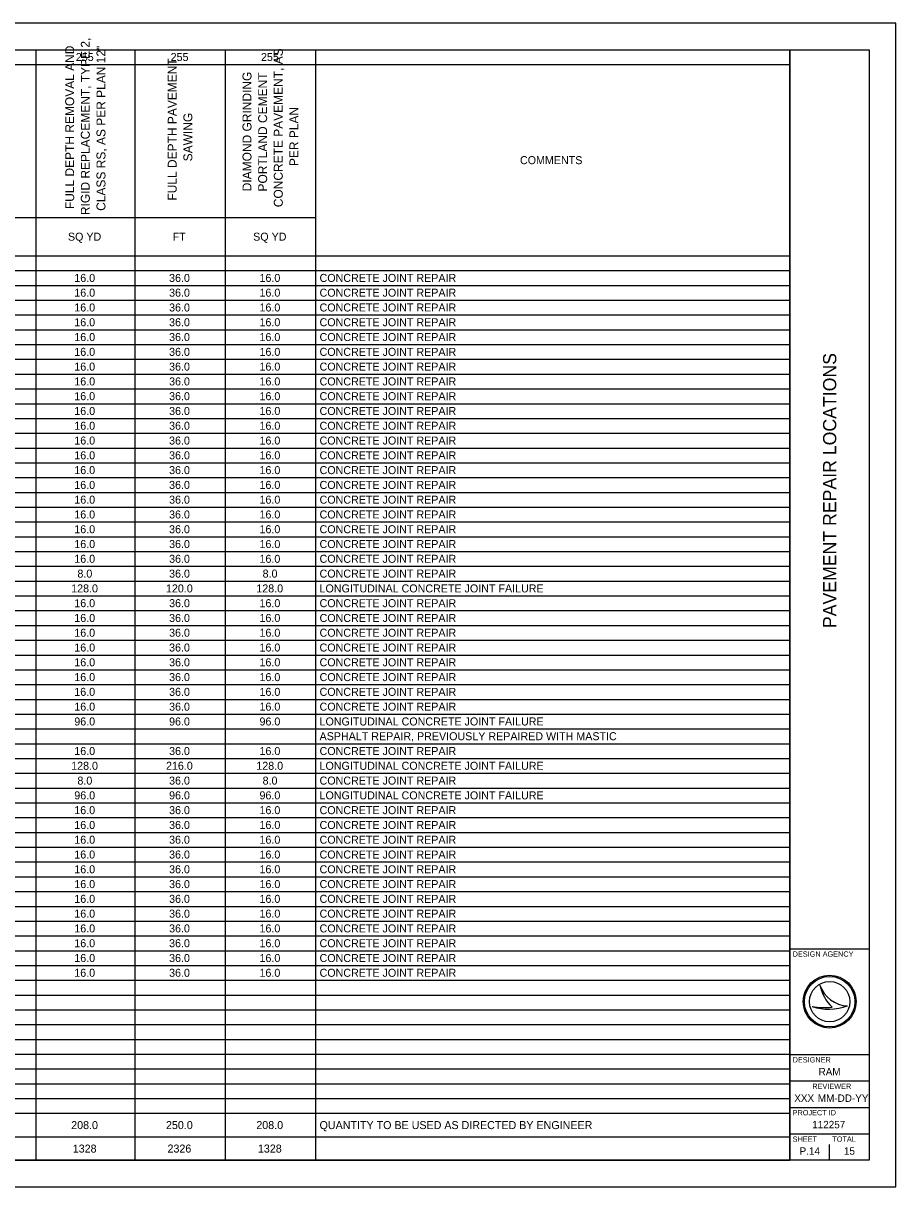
# Model space of a CAD drawing. Extents: x 0 to 34, y 0 to 22.
# Drawn here: x 17.5 to 34, y 0 to 22 of the extents above; entities that cross this region are included whole.
import ezdxf

# ---------------------------------------------------------------- set-up
doc = ezdxf.new("R2010")
doc.units = 0
for name, color, linetype in [('SH_Border', 7, 'Continuous'), ('SH_Cut_Line', 7, 'Continuous'), ('SH_Data', 7, 'Continuous'), ('SH_Text', 7, 'Continuous')]:
    doc.layers.add(name, color=color, linetype=linetype)

msp = doc.modelspace()

# ---------------------------------------------------------------- linework, layer by layer
at = {"layer": 'SH_Border'}
for p, q in [((32, 0.5), (32, 21.5)), ((32, 4.5), (33.5, 4.5)), ((32, 2.5), (33.5, 2.5)), ((32, 2), (33.5, 2)), ((32, 1.5), (33.5, 1.5)), ((32, 1), (33.5, 1))]:
    msp.add_line(p, q, dxfattribs=at)
msp.add_lwpolyline([(1.5, 21.5), (33.5, 21.5), (33.5, 0.5), (1.5, 0.5)], close=True, dxfattribs=at)
at = {"layer": 'SH_Cut_Line'}
msp.add_lwpolyline([(0, 0), (34, 0), (34, 22), (0, 22)], close=True, dxfattribs=at)
at = {"layer": 'SH_Data'}
for p, q in [((32.567, 3.81), (32.567, 3.81)), ((32.417, 3.41), (32.417, 3.41)), ((32.75, 3.5), (32.75, 3.5)), ((33.087, 3.419), (33.087, 3.419)), ((32.375, 0.675), (32.375, 0.675)), ((32.75, 0.5), (32.75, 0.8))]:
    msp.add_line(p, q, dxfattribs=at)
for radius in [0.5, 0.477, 0.477, 0.382]:
    msp.add_circle((32.75, 3.5), radius, dxfattribs=at)
for centre, radius, start, end in [((33.116, 3.998), 0.58, 198.9257, 198.9319), ((33.347, 3.97), 0.796, 191.6379, 191.6421), ((33.116, 3.998), 0.58, 198.9319, 267.1657), ((33.347, 3.97), 0.796, 191.6421, 226.0947), ((32.739, 4.37), 1.013, 251.4576, 290.0832), ((32.648, 4.654), 1.266, 259.4964, 259.4995), ((32.739, 4.37), 1.013, 251.4527, 251.4576), ((32.648, 4.654), 1.266, 259.4995, 276.6672)]:
    msp.add_arc(centre, radius, start, end, dxfattribs=at)
at = {"layer": 'SH_Text'}
for p, q in [((1.5, 21.5), (32, 21.5)), ((17.734, 21.5), (17.734, 0.5)), ((19.609, 21.5), (19.609, 0.5)), ((21.319, 21.5), (21.319, 0.5)), ((23.028, 21.5), (23.028, 21.22)), ((32, 21.5), (32, 0.5)), ((1.5, 21.22), (32, 21.22)), ((23.028, 21.22), (23.028, 17.603)), ((8.946, 18.326), (23.028, 18.326)), ((1.5, 17.603), (32, 17.603)), ((23.028, 17.603), (23.028, 1.388)), ((1.5, 17.323), (32, 17.323)), ((1.5, 17.043), (32, 17.043)), ((1.5, 16.764), (32, 16.764)), ((1.5, 16.484), (32, 16.484)), ((1.5, 16.205), (32, 16.205)), ((1.5, 15.925), (32, 15.925)), ((1.5, 15.646), (32, 15.646)), ((1.5, 15.366), (32, 15.366)), ((1.5, 15.087), (32, 15.087)), ((1.5, 14.807), (32, 14.807)), ((1.5, 14.527), (32, 14.527)), ((1.5, 14.248), (32, 14.248)), ((1.5, 13.968), (32, 13.968)), ((1.5, 13.689), (32, 13.689)), ((1.5, 13.409), (32, 13.409)), ((1.5, 13.13), (32, 13.13)), ((1.5, 12.85), (32, 12.85)), ((1.5, 12.57), (32, 12.57)), ((1.5, 12.291), (32, 12.291)), ((1.5, 12.011), (32, 12.011)), ((1.5, 11.732), (32, 11.732)), ((1.5, 11.452), (32, 11.452)), ((1.5, 11.173), (32, 11.173)), ((1.5, 10.893), (32, 10.893)), ((1.5, 10.614), (32, 10.614)), ((1.5, 10.334), (32, 10.334)), ((1.5, 10.054), (32, 10.054)), ((1.5, 9.775), (32, 9.775)), ((1.5, 9.495), (32, 9.495)), ((1.5, 9.216), (32, 9.216)), ((1.5, 8.936), (32, 8.936)), ((1.5, 8.657), (32, 8.657)), ((1.5, 8.377), (32, 8.377)), ((1.5, 8.097), (32, 8.097)), ((1.5, 7.818), (32, 7.818)), ((1.5, 7.538), (32, 7.538)), ((1.5, 7.259), (32, 7.259)), ((1.5, 6.979), (32, 6.979)), ((1.5, 6.7), (32, 6.7)), ((1.5, 6.42), (32, 6.42)), ((1.5, 6.141), (32, 6.141)), ((1.5, 5.861), (32, 5.861)), ((1.5, 5.581), (32, 5.581)), ((1.5, 5.302), (32, 5.302)), ((1.5, 5.022), (32, 5.022)), ((1.5, 4.743), (32, 4.743)), ((1.5, 4.463), (32, 4.463)), ((1.5, 4.184), (32, 4.184)), ((1.5, 3.904), (32, 3.904)), ((1.5, 3.625), (32, 3.625)), ((1.5, 3.345), (32, 3.345)), ((1.5, 3.065), (32, 3.065)), ((1.5, 2.786), (32, 2.786)), ((1.5, 2.506), (32, 2.506)), ((1.5, 2.227), (32, 2.227)), ((1.5, 1.947), (32, 1.947)), ((1.5, 1.668), (32, 1.668)), ((1.5, 1.388), (32, 1.388)), ((23.028, 1.388), (23.028, 0.5)), ((1.5, 0.944), (32, 0.944)), ((1.5, 0.5), (32, 0.5))]:
    msp.add_line(p, q, dxfattribs=at)

# ---------------------------------------------------------------- texts
at = {"layer": 'SH_Data'}
msp.add_text('PAVEMENT REPAIR LOCATIONS', height=0.25, rotation=90, dxfattribs=at).set_placement((32.875, 10.563))
for s, height, p in [('DESIGN AGENCY', 0.1, (32.05, 4.35)), ('DESIGNER', 0.1, (32.05, 2.35)), ('RAM', 0.14, (32.541, 2.105)), ('REVIEWER', 0.1, (32.422, 1.85)), ('XXX', 0.14, (32.081, 1.605)), ('MM-DD-YY', 0.14, (32.527, 1.605)), ('PROJECT ID', 0.1, (32.05, 1.35)), ('112257', 0.14, (32.42, 1.105)), ('SHEET', 0.1, (32.05, 0.85)), ('TOTAL', 0.1, (32.8, 0.85)), ('P.14', 0.14, (32.182, 0.605)), ('15', 0.14, (33.02, 0.605))]:
    msp.add_text(s, height=height, dxfattribs=at).set_placement(p)
at = {"layer": 'SH_Text'}
for s, height, p in [('FULL DEPTH REMOVAL AND ', 0.16914, (18.46, 18.486)), ('RIGID REPLACEMENT, TYPE 2, ', 0.16914, (18.756, 18.372)), ('CLASS RS, AS PER PLAN 12"', 0.16914, (19.052, 18.453)), ('CONCRETE PAVEMENT, AS ', 0.16914, (22.406, 18.522)), ('FULL DEPTH PAVEMENT ', 0.16914, (20.4, 18.647)), ('DIAMOND GRINDING ', 0.16914, (21.814, 18.823)), ('PORTLAND CEMENT ', 0.16914, (22.11, 18.819)), ('SAWING', 0.1691, (20.696, 19.39)), ('PER PLAN', 0.1691, (22.702, 19.3))]:
    msp.add_text(s, height=height, rotation=90, dxfattribs=at).set_placement(p)
for s, height, p in [('255', 0.1513, (18.492, 21.286)), ('255', 0.1513, (20.285, 21.286)), ('255', 0.1513, (21.994, 21.286)), ('COMMENTS', 0.1513, (26.893, 19.336)), ('SQ YD', 0.1513, (18.343, 17.889)), ('FT', 0.1513, (20.323, 17.889)), ('SQ YD', 0.1513, (21.846, 17.889)), ('16.0', 0.1513, (18.463, 17.109)), ('36.0', 0.1513, (20.256, 17.109)), ('16.0', 0.1513, (21.966, 17.109)), ('CONCRETE JOINT REPAIR', 0.15129, (23.102, 17.109)), ('16.0', 0.1513, (18.463, 16.83)), ('36.0', 0.1513, (20.256, 16.83)), ('16.0', 0.1513, (21.966, 16.83)), ('CONCRETE JOINT REPAIR', 0.15129, (23.102, 16.83)), ('16.0', 0.1513, (18.463, 16.55)), ('36.0', 0.1513, (20.256, 16.55)), ('16.0', 0.1513, (21.966, 16.55)), ('CONCRETE JOINT REPAIR', 0.15129, (23.102, 16.55)), ('16.0', 0.1513, (18.463, 16.271)), ('36.0', 0.1513, (20.256, 16.271)), ('16.0', 0.1513, (21.966, 16.271)), ('CONCRETE JOINT REPAIR', 0.15129, (23.102, 16.271)), ('16.0', 0.1513, (18.463, 15.991)), ('36.0', 0.1513, (20.256, 15.991)), ('16.0', 0.1513, (21.966, 15.991)), ('CONCRETE JOINT REPAIR', 0.15129, (23.102, 15.991)), ('16.0', 0.1513, (18.463, 15.711)), ('36.0', 0.1513, (20.256, 15.711)), ('16.0', 0.1513, (21.966, 15.711)), ('CONCRETE JOINT REPAIR', 0.15129, (23.102, 15.711)), ('16.0', 0.1513, (18.463, 15.432)), ('36.0', 0.1513, (20.256, 15.432)), ('16.0', 0.1513, (21.966, 15.432)), ('CONCRETE JOINT REPAIR', 0.15129, (23.102, 15.432)), ('16.0', 0.1513, (18.463, 15.152)), ('36.0', 0.1513, (20.256, 15.152)), ('16.0', 0.1513, (21.966, 15.152)), ('CONCRETE JOINT REPAIR', 0.15129, (23.102, 15.152)), ('16.0', 0.1513, (18.463, 14.873)), ('36.0', 0.1513, (20.256, 14.873)), ('16.0', 0.1513, (21.966, 14.873)), ('CONCRETE JOINT REPAIR', 0.15129, (23.102, 14.873)), ('16.0', 0.1513, (18.463, 14.593)), ('36.0', 0.1513, (20.256, 14.593)), ('16.0', 0.1513, (21.966, 14.593)), ('CONCRETE JOINT REPAIR', 0.15129, (23.102, 14.593)), ('16.0', 0.1513, (18.463, 14.314)), ('36.0', 0.1513, (20.256, 14.314)), ('16.0', 0.1513, (21.966, 14.314)), ('CONCRETE JOINT REPAIR', 0.15129, (23.102, 14.314)), ('16.0', 0.1513, (18.463, 14.034)), ('36.0', 0.1513, (20.256, 14.034)), ('16.0', 0.1513, (21.966, 14.034)), ('CONCRETE JOINT REPAIR', 0.15129, (23.102, 14.034)), ('16.0', 0.1513, (18.463, 13.755)), ('36.0', 0.1513, (20.256, 13.755)), ('16.0', 0.1513, (21.966, 13.755)), ('CONCRETE JOINT REPAIR', 0.15129, (23.102, 13.755)), ('16.0', 0.1513, (18.463, 13.475)), ('36.0', 0.1513, (20.256, 13.475)), ('16.0', 0.1513, (21.966, 13.475)), ('CONCRETE JOINT REPAIR', 0.15129, (23.102, 13.475)), ('16.0', 0.1513, (18.463, 13.195)), ('36.0', 0.1513, (20.256, 13.195)), ('16.0', 0.1513, (21.966, 13.195)), ('CONCRETE JOINT REPAIR', 0.15129, (23.102, 13.195)), ('16.0', 0.1513, (18.463, 12.916)), ('36.0', 0.1513, (20.256, 12.916)), ('16.0', 0.1513, (21.966, 12.916)), ('CONCRETE JOINT REPAIR', 0.15129, (23.102, 12.916)), ('16.0', 0.1513, (18.463, 12.636)), ('36.0', 0.1513, (20.256, 12.636)), ('16.0', 0.1513, (21.966, 12.636)), ('CONCRETE JOINT REPAIR', 0.15129, (23.102, 12.636)), ('16.0', 0.1513, (18.463, 12.357)), ('36.0', 0.1513, (20.256, 12.357)), ('16.0', 0.1513, (21.966, 12.357)), ('CONCRETE JOINT REPAIR', 0.15129, (23.102, 12.357)), ('16.0', 0.1513, (18.463, 12.077)), ('36.0', 0.1513, (20.256, 12.077)), ('16.0', 0.1513, (21.966, 12.077)), ('CONCRETE JOINT REPAIR', 0.15129, (23.102, 12.077)), ('16.0', 0.1513, (18.463, 11.798)), ('36.0', 0.1513, (20.256, 11.798)), ('16.0', 0.1513, (21.966, 11.798)), ('CONCRETE JOINT REPAIR', 0.15129, (23.102, 11.798)), ('8.0', 0.1513, (18.522, 11.518)), ('36.0', 0.1513, (20.256, 11.518)), ('8.0', 0.1513, (22.025, 11.518)), ('CONCRETE JOINT REPAIR', 0.15129, (23.102, 11.518)), ('128.0', 0.1513, (18.404, 11.238)), ('120.0', 0.1513, (20.197, 11.238)), ('128.0', 0.1513, (21.906, 11.238)), ('LONGITUDINAL CONCRETE JOINT FAILURE', 0.15129, (23.102, 11.238)), ('16.0', 0.1513, (18.463, 10.959)), ('36.0', 0.1513, (20.256, 10.959)), ('16.0', 0.1513, (21.966, 10.959)), ('CONCRETE JOINT REPAIR', 0.15129, (23.102, 10.959)), ('16.0', 0.1513, (18.463, 10.679)), ('36.0', 0.1513, (20.256, 10.679)), ('16.0', 0.1513, (21.966, 10.679)), ('CONCRETE JOINT REPAIR', 0.15129, (23.102, 10.679)), ('16.0', 0.1513, (18.463, 10.4)), ('36.0', 0.1513, (20.256, 10.4)), ('16.0', 0.1513, (21.966, 10.4)), ('CONCRETE JOINT REPAIR', 0.15129, (23.102, 10.4)), ('16.0', 0.1513, (18.463, 10.12)), ('36.0', 0.1513, (20.256, 10.12)), ('16.0', 0.1513, (21.966, 10.12)), ('CONCRETE JOINT REPAIR', 0.15129, (23.102, 10.12)), ('16.0', 0.1513, (18.463, 9.841)), ('36.0', 0.1513, (20.256, 9.841)), ('16.0', 0.1513, (21.966, 9.841)), ('CONCRETE JOINT REPAIR', 0.15129, (23.102, 9.841)), ('16.0', 0.1513, (18.463, 9.561)), ('36.0', 0.1513, (20.256, 9.561)), ('16.0', 0.1513, (21.966, 9.561)), ('CONCRETE JOINT REPAIR', 0.15129, (23.102, 9.561)), ('16.0', 0.1513, (18.463, 9.282)), ('36.0', 0.1513, (20.256, 9.282)), ('16.0', 0.1513, (21.966, 9.282)), ('CONCRETE JOINT REPAIR', 0.15129, (23.102, 9.282)), ('16.0', 0.1513, (18.463, 9.002)), ('36.0', 0.1513, (20.256, 9.002)), ('16.0', 0.1513, (21.966, 9.002)), ('CONCRETE JOINT REPAIR', 0.15129, (23.102, 9.002)), ('96.0', 0.1513, (18.463, 8.722)), ('96.0', 0.1513, (20.256, 8.722)), ('96.0', 0.1513, (21.966, 8.722)), ('LONGITUDINAL CONCRETE JOINT FAILURE', 0.15129, (23.102, 8.722)), ('ASPHALT REPAIR, PREVIOUSLY REPAIRED WITH MASTIC', 0.15129, (23.102, 8.443)), ('16.0', 0.1513, (18.463, 8.163)), ('36.0', 0.1513, (20.256, 8.163)), ('16.0', 0.1513, (21.966, 8.163)), ('CONCRETE JOINT REPAIR', 0.15129, (23.102, 8.163)), ('128.0', 0.1513, (18.404, 7.884)), ('216.0', 0.1513, (20.197, 7.884)), ('128.0', 0.1513, (21.906, 7.884)), ('LONGITUDINAL CONCRETE JOINT FAILURE', 0.15129, (23.102, 7.884)), ('8.0', 0.1513, (18.522, 7.604)), ('36.0', 0.1513, (20.256, 7.604)), ('8.0', 0.1513, (22.025, 7.604)), ('CONCRETE JOINT REPAIR', 0.15129, (23.102, 7.604)), ('96.0', 0.1513, (18.463, 7.325)), ('96.0', 0.1513, (20.256, 7.325)), ('96.0', 0.1513, (21.966, 7.325)), ('LONGITUDINAL CONCRETE JOINT FAILURE', 0.15129, (23.102, 7.325)), ('16.0', 0.1513, (18.463, 7.045)), ('36.0', 0.1513, (20.256, 7.045)), ('16.0', 0.1513, (21.966, 7.045)), ('CONCRETE JOINT REPAIR', 0.15129, (23.102, 7.045)), ('16.0', 0.1513, (18.463, 6.765)), ('36.0', 0.1513, (20.256, 6.765)), ('16.0', 0.1513, (21.966, 6.765)), ('CONCRETE JOINT REPAIR', 0.15129, (23.102, 6.765)), ('16.0', 0.1513, (18.463, 6.486)), ('36.0', 0.1513, (20.256, 6.486)), ('16.0', 0.1513, (21.966, 6.486)), ('CONCRETE JOINT REPAIR', 0.15129, (23.102, 6.486)), ('16.0', 0.1513, (18.463, 6.206)), ('36.0', 0.1513, (20.256, 6.206)), ('16.0', 0.1513, (21.966, 6.206)), ('CONCRETE JOINT REPAIR', 0.15129, (23.102, 6.206)), ('16.0', 0.1513, (18.463, 5.927)), ('36.0', 0.1513, (20.256, 5.927)), ('16.0', 0.1513, (21.966, 5.927)), ('CONCRETE JOINT REPAIR', 0.15129, (23.102, 5.927)), ('16.0', 0.1513, (18.463, 5.647)), ('36.0', 0.1513, (20.256, 5.647)), ('16.0', 0.1513, (21.966, 5.647)), ('CONCRETE JOINT REPAIR', 0.15129, (23.102, 5.647)), ('16.0', 0.1513, (18.463, 5.368)), ('36.0', 0.1513, (20.256, 5.368)), ('16.0', 0.1513, (21.966, 5.368)), ('CONCRETE JOINT REPAIR', 0.15129, (23.102, 5.368)), ('16.0', 0.1513, (18.463, 5.088)), ('36.0', 0.1513, (20.256, 5.088)), ('16.0', 0.1513, (21.966, 5.088)), ('CONCRETE JOINT REPAIR', 0.15129, (23.102, 5.088)), ('16.0', 0.1513, (18.463, 4.809)), ('36.0', 0.1513, (20.256, 4.809)), ('16.0', 0.1513, (21.966, 4.809)), ('CONCRETE JOINT REPAIR', 0.15129, (23.102, 4.809)), ('16.0', 0.1513, (18.463, 4.529)), ('36.0', 0.1513, (20.256, 4.529)), ('16.0', 0.1513, (21.966, 4.529)), ('CONCRETE JOINT REPAIR', 0.15129, (23.102, 4.529)), ('16.0', 0.1513, (18.463, 4.249)), ('36.0', 0.1513, (20.256, 4.249)), ('16.0', 0.1513, (21.966, 4.249)), ('CONCRETE JOINT REPAIR', 0.15129, (23.102, 4.249)), ('16.0', 0.1513, (18.463, 3.97)), ('36.0', 0.1513, (20.256, 3.97)), ('16.0', 0.1513, (21.966, 3.97)), ('CONCRETE JOINT REPAIR', 0.15129, (23.102, 3.97)), ('208.0', 0.1513, (18.404, 1.09)), ('250.0', 0.1513, (20.197, 1.09)), ('208.0', 0.1513, (21.906, 1.09)), ('QUANTITY TO BE USED AS DIRECTED BY ENGINEER', 0.15129, (23.102, 1.09)), ('1328', 0.1513, (18.434, 0.646)), ('2326', 0.1513, (20.226, 0.646)), ('1328', 0.1513, (21.936, 0.646))]:
    msp.add_text(s, height=height, dxfattribs=at).set_placement(p)

doc.saveas('drawing.dxf')
